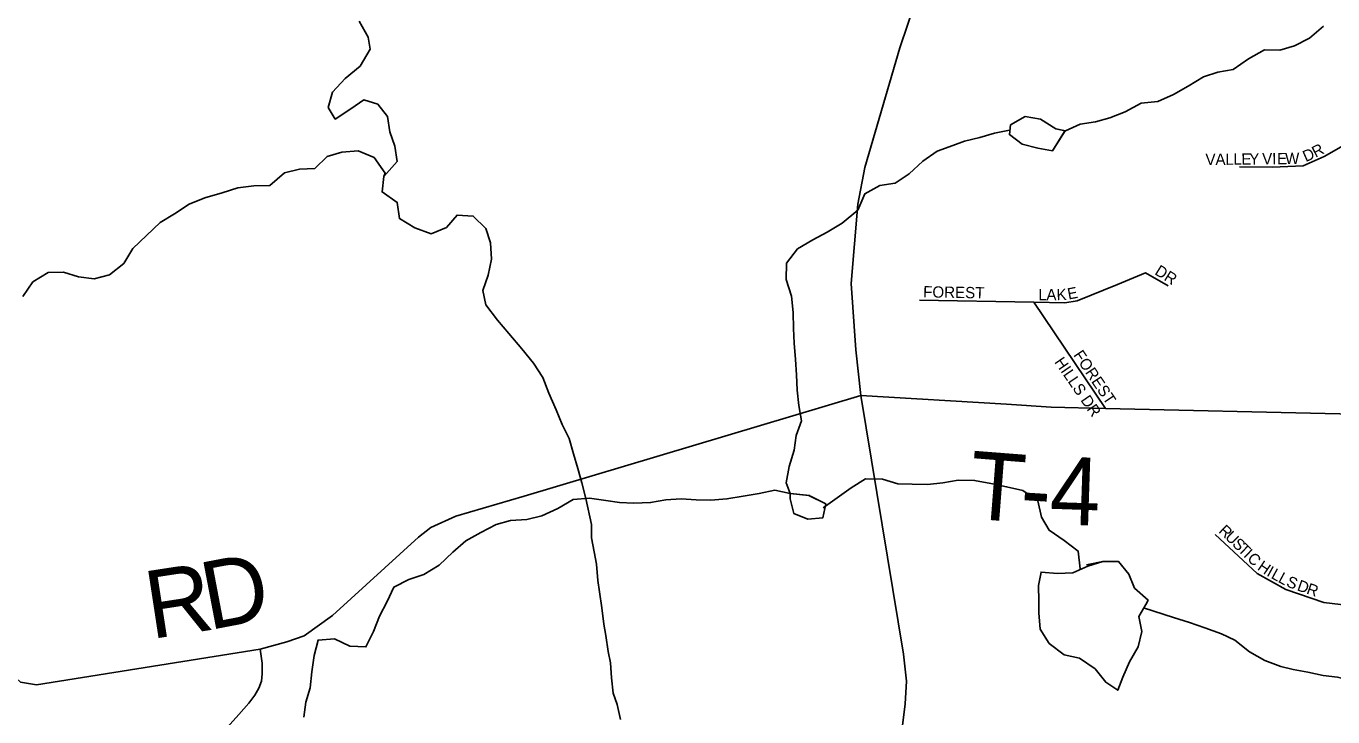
# Model space of a CAD drawing. Extents: x 1985906 to 2277390, y 930619 to 1324581.
# Drawn here: x 2154255 to 2160035, y 1139964 to 1143019 of the extents above; entities that cross this region are included whole.
import ezdxf

# ---------------------------------------------------------------- set-up
doc = ezdxf.new("R2010")
doc.units = 0
for name, color, linetype in [('GM_X_County_Road', 7, 'Continuous'), ('GM_X_County_Road_Text', 7, 'Continuous'), ('GM_X_Major_River', 7, 'Continuous'), ('GM_X_Minor_Lake', 7, 'Continuous'), ('GM_X_Minor_River', 7, 'Continuous'), ('GM_X_Township_Road', 7, 'Continuous'), ('GM_X_Township_Road_Text', 7, 'Continuous'), ('GM_X_Township_Subdivision', 7, 'Continuous'), ('GM_X_Township_Subdivision_Text', 7, 'Continuous')]:
    doc.layers.add(name, color=color, linetype=linetype)

msp = doc.modelspace()

# ---------------------------------------------------------------- linework, layer by layer
at = {"layer": 'GM_X_County_Road'}
for points in [[(2157947.9, 1141385.9), (2157925.7, 1141588), (2157904.4, 1141880.4), (2157933.3, 1142232.2), (2157964.4, 1142394.7), (2158120.1, 1142924), (2158223.8, 1143235.3)], [(2150832.3, 1141226.9), (2150929.5, 1141177.2), (2151726.2, 1140689.3), (2151987.7, 1140530), (2152039.8, 1140514.5), (2152134, 1140489.5), (2152181, 1140488), (2152445.8, 1140479.1), (2153592.7, 1140472.1), (2153744.6, 1140459.8), (2153873, 1140417.2), (2153989.8, 1140336.4), (2154230, 1140116.7), (2154300.1, 1140105.4), (2155289.5, 1140263.1), (2155408.5, 1140295.8), (2155484.3, 1140322.6), (2155610.7, 1140411.9), (2155991, 1140758.1), (2156044.5, 1140800.8), (2156155.8, 1140852.2), (2156458.5, 1140939.8), (2157947.9, 1141385.9)], [(2157913, 1137779.4), (2157960.6, 1138246.4), (2158037.3, 1139165.3), (2158066.7, 1139403.4), (2158143, 1140021.3), (2158149.9, 1140121.6), (2158136.6, 1140241.7), (2157947.9, 1141385.9)]]:
    msp.add_lwpolyline(points, dxfattribs=at)
at = {"layer": 'GM_X_Major_River'}
for points in [[(2156730.5, 1140930.1), (2156713.3, 1140998.3), (2156695.9, 1141062), (2156676.4, 1141127.7), (2156656.9, 1141195.3), (2156625.5, 1141256.7), (2156600.1, 1141322.2), (2156566.4, 1141395.6), (2156540.9, 1141465.1), (2156499.5, 1141528.3), (2156448.1, 1141591.2), (2156390.6, 1141660), (2156339.3, 1141718.9), (2156287.9, 1141785.9), (2156274.4, 1141849.7), (2156298.8, 1141918.4), (2156313.2, 1141988.8), (2156309.5, 1142060.9), (2156288.1, 1142124.5), (2156232.9, 1142179.3), (2156160.9, 1142183.7), (2156114.3, 1142128.5), (2156047, 1142100.9), (2155974.5, 1142127.2), (2155905.7, 1142167.7), (2155896.1, 1142239.6), (2155829.1, 1142286.2), (2155837.5, 1142354.5), (2155895.9, 1142420), (2155886.4, 1142487.9), (2155863, 1142551.4), (2155853.4, 1142619.4), (2155810.2, 1142674.5), (2155747.9, 1142693.1), (2155690.9, 1142653.6), (2155622, 1142608), (2155590.9, 1142659.4), (2155609.3, 1142727.9), (2155665.8, 1142787.3), (2155732.4, 1142843), (2155776.6, 1142918.1), (2155767.5, 1142970), (2155727.9, 1143041.2)], [(2156884, 1139951.6), (2156869.9, 1140017.7), (2156851.9, 1140067.8), (2156843.8, 1140135.9), (2156839.8, 1140202.1), (2156829.7, 1140252.1), (2156819.7, 1140324.3), (2156809.6, 1140374.4), (2156801.6, 1140446.5), (2156791.5, 1140516.7), (2156783.5, 1140566.8), (2156777.4, 1140638.9), (2156767.4, 1140693), (2156755.3, 1140755.1), (2156755.3, 1140815.2), (2156730.5, 1140930.1)]]:
    msp.add_lwpolyline(points, dxfattribs=at)
at = {"layer": 'GM_X_Minor_Lake'}
for points in [[(2158851.1, 1142556.1), (2158810.4, 1142565.5), (2158742.5, 1142607.5), (2158674.5, 1142619.5), (2158608.7, 1142583.4)], [(2158852.3, 1142555.8), (2158810.4, 1142565.5), (2158742.5, 1142607.5), (2158674.5, 1142619.5), (2158608.7, 1142583.4)], [(2158608.7, 1142583.4), (2158604.7, 1142539.3), (2158660.6, 1142497.3), (2158730.5, 1142479.3), (2158794.4, 1142467.3), (2158851.1, 1142556.1)], [(2158608.7, 1142583.4), (2158604.7, 1142539.3), (2158660.6, 1142497.3), (2158730.5, 1142479.3), (2158794.4, 1142467.3), (2158848.9, 1142552.6)], [(2157634.8, 1140952.4), (2157634.5, 1140927.9), (2157650.5, 1140863.8), (2157712.5, 1140837.8), (2157778.4, 1140843.8), (2157792.3, 1140905.9), (2157717.5, 1140943.4)], [(2157634.8, 1140952.4), (2157634.5, 1140927.9), (2157650.5, 1140863.8), (2157712.5, 1140837.8), (2157778.4, 1140843.8), (2157792.3, 1140905.9), (2157724.4, 1140940)], [(2157717.5, 1140943.4), (2157634.8, 1140952.4)], [(2157634.8, 1140952.4), (2157722.1, 1140942.9)], [(2159208.7, 1140460.3), (2159218.3, 1140480.5), (2159157.5, 1140533.5), (2159132.4, 1140595.2), (2159087.5, 1140650.5), (2159017.6, 1140651.3), (2158946, 1140636)], [(2159208.7, 1140460.3), (2159218.3, 1140480.5), (2159157.5, 1140533.5), (2159132.4, 1140595.2), (2159087.5, 1140650.5), (2159017.6, 1140651.3), (2158952.1, 1140630.1)], [(2158952.1, 1140630.1), (2158884.7, 1140600.9), (2158816.8, 1140597.7), (2158744.8, 1140604.4), (2158733.9, 1140544.1), (2158735.1, 1140476), (2158734, 1140423.9), (2158741.3, 1140351.9), (2158780.3, 1140288.5), (2158847.1, 1140237.5), (2158915.3, 1140222.7), (2158984, 1140175.8), (2159031, 1140116.6), (2159083.5, 1140081.4), (2159106.5, 1140139.9), (2159135.3, 1140206.6), (2159174, 1140273.4), (2159190.8, 1140341.8), (2159177.7, 1140407.7), (2159208.7, 1140460.3)]]:
    msp.add_lwpolyline(points, dxfattribs=at)
at = {"layer": 'GM_X_Minor_River'}
for points in [[(2158852.3, 1142555.8), (2158917.7, 1142585), (2158985.4, 1142596.2), (2159049, 1142613.4), (2159116.4, 1142640.6), (2159187.7, 1142677.9), (2159261.4, 1142685.3), (2159330.8, 1142716.5), (2159396, 1142753.8), (2159463.2, 1142795), (2159526.7, 1142816.2), (2159594.4, 1142827.4), (2159661.5, 1142874.6), (2159732.7, 1142914), (2159800.6, 1142913.2), (2159866.2, 1142932.3), (2159931.5, 1142965.6), (2159994.5, 1143018.8)], [(2157634.8, 1140952.4), (2157617.5, 1140999.3), (2157630.2, 1141071.6), (2157652.9, 1141144.1), (2157661.7, 1141208.4), (2157684.5, 1141272.9), (2157673.4, 1141340.9), (2157666.2, 1141408.8), (2157663, 1141476.9), (2157657.8, 1141545), (2157652.5, 1141617), (2157649.4, 1141681.1), (2157648.1, 1141753.2), (2157640.9, 1141825.2), (2157617.6, 1141898.9), (2157618.3, 1141971), (2157667.2, 1142034), (2157734.4, 1142073.3), (2157797.7, 1142108.4), (2157864.9, 1142147.7), (2157933.8, 1142205), (2157964.4, 1142277.7), (2158031.7, 1142314.9), (2158099.4, 1142324.1), (2158160.6, 1142365.3), (2158221.5, 1142422.5), (2158284.7, 1142465.7), (2158354.1, 1142490.9), (2158405.7, 1142509.9), (2158473.3, 1142527.1), (2158538.9, 1142546.3), (2158604.6, 1142559.5)], [(2155837.5, 1142354.5), (2155843.2, 1142368.6), (2155793.7, 1142437.6), (2155723.1, 1142468.1), (2155651.3, 1142462.4), (2155585.9, 1142442.8), (2155531.2, 1142389.5), (2155463.4, 1142385.9), (2155397.8, 1142370.3), (2155333.2, 1142314.7), (2155261.4, 1142313.1), (2155191.7, 1142303.4), (2155122.3, 1142281.8), (2155044.9, 1142260), (2154975.7, 1142232.3), (2154910.8, 1142188.7), (2154847.8, 1142151.2), (2154726.6, 1142036.2), (2154686.2, 1141969.1), (2154623.4, 1141919.6), (2154556, 1141902), (2154485.9, 1141910.4), (2154419.5, 1141930.9), (2154351.6, 1141929.3), (2154284.7, 1141887.7), (2154240.3, 1141822.6)], [(2158918.2, 1140618.7), (2158908.4, 1140697.2), (2158846.4, 1140743.2), (2158780.4, 1140789.3), (2158746.4, 1140847.4), (2158730.3, 1140919.5), (2158664.3, 1140965.5), (2158592.3, 1140981.5), (2158522.4, 1140995.4), (2158450.4, 1141009.4), (2158378.4, 1141011.3), (2158310.4, 1140999.2), (2158242.5, 1140991.1), (2158174.5, 1140993.1), (2158110.5, 1140995), (2158042.5, 1141015), (2157968.6, 1141016.9), (2157904.6, 1140976.8), (2157780.7, 1140887.7)], [(2155482.6, 1139962.2), (2155492.5, 1140028.3), (2155510.5, 1140092.5), (2155518.4, 1140162.6), (2155528.3, 1140234.8), (2155546.3, 1140303), (2155618.2, 1140309.1), (2155686.2, 1140277.1), (2155758.2, 1140273.1), (2155792.1, 1140341.3), (2155818.1, 1140409.5), (2155852, 1140473.6), (2155881.9, 1140537.8), (2155947.9, 1140571.9), (2156013.8, 1140594), (2156081.7, 1140634.2), (2156141.7, 1140692.4), (2156199.6, 1140742.5), (2156265.5, 1140778.7), (2156333.5, 1140814.8), (2156397.4, 1140832.9), (2156469.4, 1140837), (2156535.4, 1140853.1), (2156607.3, 1140885.2), (2156675.2, 1140925.4), (2156747.2, 1140931.5), (2156819.2, 1140921.5), (2156879.2, 1140911.6), (2156943.1, 1140909.6), (2157017.1, 1140911.7), (2157085.1, 1140923.8), (2157153, 1140927.9), (2157219, 1140923.9), (2157283, 1140922), (2157354.9, 1140928.1), (2157426.9, 1140940.2), (2157496.8, 1140952.3), (2157566.8, 1140966.4), (2157634.8, 1140952.4)], [(2160264.4, 1140021.1), (2160194.4, 1140021.1), (2160140.4, 1140057.1), (2160118.4, 1140125.2), (2160056.4, 1140139.2), (2159992.4, 1140147.1), (2159924.4, 1140161.1), (2159860.4, 1140173.1), (2159804.5, 1140187), (2159734.5, 1140213), (2159666.5, 1140251), (2159602.4, 1140303.1), (2159542.5, 1140331.1), (2159468.5, 1140357.1), (2159400.5, 1140381), (2159330.5, 1140403), (2159197.4, 1140446.2)]]:
    msp.add_lwpolyline(points, dxfattribs=at)
at = {"layer": 'GM_X_Township_Road'}
msp.add_lwpolyline([(2157947.9, 1141385.9), (2158591.7, 1141347.2), (2158789.7, 1141333.4), (2159029.2, 1141327.9), (2160066.7, 1141304), (2160163.9, 1141299.2)], dxfattribs=at)
at = {"layer": 'GM_X_Township_Subdivision'}
for points in [[(2160082.4, 1142490.9), (2159997, 1142442), (2159903.3, 1142401.3), (2159769, 1142395.2), (2159622.9, 1142397.2)], [(2158207, 1141807.7), (2158712.6, 1141797.8), (2158850.4, 1141795.1), (2158904.3, 1141803.7), (2159083.3, 1141875.9), (2159206.6, 1141927.4), (2159307.1, 1141870.5)], [(2159029.2, 1141327.9), (2158712.6, 1141797.8)], [(2159515.2, 1140770.6), (2159700.9, 1140598.4), (2159827.6, 1140527.7), (2159996.1, 1140469.5), (2160204.4, 1140445.1)], [(2155148.5, 1139222.5), (2155148.2, 1139222.8), (2155073.8, 1139294.2), (2155027.7, 1139358.2), (2154995, 1139429.5), (2154978.6, 1139477.1), (2154972.7, 1139509.8), (2154968.2, 1139561.9), (2154971.2, 1139621.4), (2154981.6, 1139679.4), (2155005.4, 1139747.8), (2155024.7, 1139780.5), (2155058.9, 1139823.6), (2155130.3, 1139902.5), (2155195, 1139973.9), (2155239.7, 1140023.7), (2155267.1, 1140059.4), (2155284.3, 1140090.6), (2155296.1, 1140121.8), (2155299.1, 1140153.8), (2155299.1, 1140200.7), (2155289.5, 1140263.1)]]:
    msp.add_lwpolyline(points, dxfattribs=at)

# ---------------------------------------------------------------- texts
at = {"layer": 'GM_X_County_Road_Text'}
for s, rotation, p in [('D', 10.77907, (2155063, 1140346.8)), ('R', 8.70195, (2154807.9, 1140307.5))]:
    msp.add_text(s, height=300, rotation=rotation, dxfattribs=at).set_placement(p)
at = {"layer": 'GM_X_Township_Road_Text'}
for s, rotation, p in [('T', 355.54279, (2158418.7, 1140842.2)), ('4', 358.09091, (2158779.9, 1140816.4)), ('-', 356.44696, (2158647.5, 1140824.5))]:
    msp.add_text(s, height=300, rotation=rotation, dxfattribs=at).set_placement(p)
at = {"layer": 'GM_X_Township_Subdivision_Text'}
for s, rotation, p in [('R', 27.16058, (2159958.7, 1142436.6)), ('V', 0.63392, (2159472.2, 1142404.7)), ('A', 0.6462, (2159516.2, 1142405.2)), ('L', 0.6284, (2159560.2, 1142405.7)), ('L', 0.64836, (2159595.4, 1142406.1)), ('E', 0.65572, (2159630.6, 1142406.5)), ('Y', 0.63392, (2159665.8, 1142406.9)), ('V', 0.6237, (2159723, 1142407.5)), ('I', 0.63677, (2159767, 1142408)), ('E', 0.65572, (2159789, 1142408.3)), ('W', 0.8301, (2159824.4, 1142408.7)), ('D', 23.78548, (2159915.5, 1142417.5)), ('DR', 327.99708, (2159243.8, 1141923.7)), ('FOREST', 358.89894, (2158222.6, 1141819.5)), ('E', 11.1416, (2158866.3, 1141809.3)), ('L', 0.32787, (2158732.9, 1141806.3)), ('A', 0.34203, (2158768.1, 1141806.5)), ('K', 1.95384, (2158813.7, 1141806.8)), ('FOREST', 303.99395, (2158885.9, 1141564.6)), ('HILLS DR', 304.46431, (2158801.7, 1141533.5)), ('R', 315.79001, (2159527, 1140782.8)), ('U', 315.78822, (2159555.4, 1140755.2)), ('S', 315.81077, (2159587, 1140724.5)), ('T', 315.79224, (2159612.2, 1140700)), ('I', 315.78504, (2159637.4, 1140675.5)), ('C', 315.79001, (2159653.2, 1140660.1)), ('H', 325.58475, (2159698.3, 1140617.4)), ('I', 331.26794, (2159739.2, 1140589.7)), ('L', 331.27605, (2159758.5, 1140579.1)), ('L', 331.78295, (2159789.8, 1140561.9)), ('S', 337.59492, (2159825.8, 1140542.9)), ('D', 340.95201, (2159873.8, 1140524.1)), ('R', 340.95987, (2159915.4, 1140509.7))]:
    msp.add_text(s, height=50, rotation=rotation, dxfattribs=at).set_placement(p)

doc.saveas('drawing.dxf')
